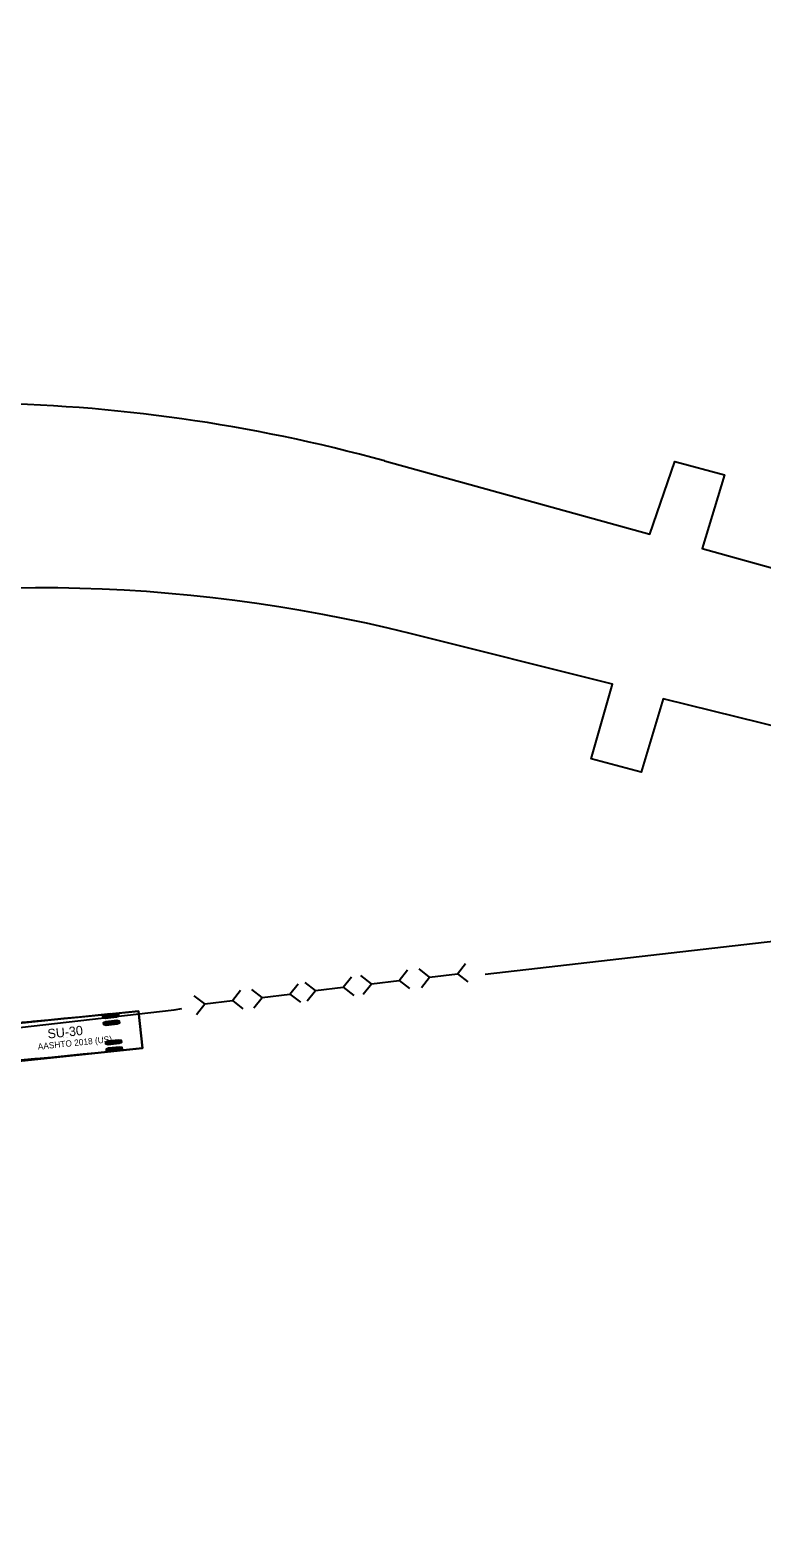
# Model space of a CAD drawing. Extents: x 1600240 to 1604759, y 285789 to 289704.
# Drawn here: x 1601319 to 1601475.5, y 286564.2 to 286886.8 of the extents above; entities that cross this region are included whole.
import ezdxf

# ---------------------------------------------------------------- set-up
doc = ezdxf.new("R2010")
doc.units = 0
for name, color, linetype in [('MT_P_Cells', 7, 'Continuous'), ('MT_P_CL_Double_Solid', 7, 'Continuous'), ('MT_X_CL_Double_Solid', 7, 'Continuous'), ('MT_X_Edge_Line', 7, 'Continuous'), ('PM_X_Edge_Line', 7, 'Continuous')]:
    doc.layers.add(name, color=color, linetype=linetype)

msp = doc.modelspace()

# ---------------------------------------------------------------- linework, layer by layer
at = {"layer": 'MT_P_Cells'}
for p, q in [((1601410.37, 286684.89), (1601412.12, 286687.12)), ((1601385.95, 286682.01), (1601387.7, 286684.24)), ((1601391.96, 286682.75), (1601389.73, 286684.5)), ((1601391.96, 286682.75), (1601397.91, 286683.47)), ((1601397.91, 286683.47), (1601399.66, 286685.7)), ((1601397.91, 286683.47), (1601400.14, 286681.73)), ((1601404.41, 286684.17), (1601402.19, 286685.92)), ((1601402.67, 286681.95), (1601404.41, 286684.17)), ((1601404.41, 286684.17), (1601410.37, 286684.89)), ((1601410.37, 286684.89), (1601412.6, 286683.15)), ((1601356.29, 286678.43), (1601354.06, 286680.18)), ((1601362.24, 286679.15), (1601363.99, 286681.38)), ((1601368.59, 286679.81), (1601366.36, 286681.56)), ((1601368.59, 286679.81), (1601374.54, 286680.53)), ((1601374.54, 286680.53), (1601376.29, 286682.76)), ((1601374.54, 286680.53), (1601376.77, 286678.79)), ((1601380, 286681.29), (1601377.77, 286683.04)), ((1601378.25, 286679.07), (1601380, 286681.29)), ((1601380, 286681.29), (1601385.95, 286682.01)), ((1601385.95, 286682.01), (1601388.18, 286680.27)), ((1601390.21, 286680.53), (1601391.96, 286682.75)), ((1601354.54, 286676.21), (1601356.29, 286678.43)), ((1601356.29, 286678.43), (1601362.24, 286679.15)), ((1601362.24, 286679.15), (1601364.47, 286677.41)), ((1601366.84, 286677.58), (1601368.59, 286679.81))]:
    msp.add_line(p, q, dxfattribs=at)
at = {"layer": 'MT_P_CL_Double_Solid'}
for p, q in [((1601342.12, 286676.92), (1601312.29, 286673.79)), ((1601342.96, 286668.97), (1601342.12, 286676.92)), ((1601334.52, 286675.92), (1601337.84, 286676.26)), ((1601334.54, 286675.71), (1601337.86, 286676.06)), ((1601334.56, 286675.5), (1601337.88, 286675.85)), ((1601334.68, 286674.42), (1601337.99, 286674.77)), ((1601334.7, 286674.22), (1601338.01, 286674.56)), ((1601334.72, 286674.01), (1601338.04, 286674.36)), ((1601335.11, 286670.28), (1601338.43, 286670.63)), ((1601335.13, 286670.07), (1601338.45, 286670.42)), ((1601313.12, 286665.84), (1601342.96, 286668.97)), ((1601335.16, 286669.87), (1601338.47, 286670.21)), ((1601335.27, 286668.79), (1601338.58, 286669.14)), ((1601335.29, 286668.58), (1601338.61, 286668.93)), ((1601335.31, 286668.37), (1601338.63, 286668.72))]:
    msp.add_line(p, q, dxfattribs=at)
for points in [[(1601317.91, 286674.52), (1601329.22, 286675.59), (1601342.12, 286676.92), (1601342.96, 286668.97), (1601341.53, 286668.81)], [(1601319.21, 286674.63), (1601316.26, 286674.37), (1601313.03, 286674.14), (1601309.8, 286673.96), (1601306.57, 286673.84), (1601303.34, 286673.79), (1601300.1, 286673.79), (1601296.87, 286673.86), (1601293.64, 286673.99), (1601290.74, 286674.16)], [(1601336.16, 286676.3), (1601332.84, 286675.95), (1601329.51, 286675.62), (1601326.19, 286675.29), (1601322.87, 286674.97), (1601319.54, 286674.66), (1601319.21, 286674.63)], [(1601341.53, 286668.81), (1601312.6, 286665.78)], [(1601336.99, 286668.34), (1601333.65, 286667.99), (1601330.31, 286667.66), (1601326.96, 286667.33), (1601323.62, 286667.01), (1601320.27, 286666.7), (1601319.94, 286666.67)], [(1601319.94, 286666.67), (1601316.92, 286666.4), (1601313.55, 286666.15), (1601310.17, 286665.97), (1601306.79, 286665.85), (1601303.4, 286665.79), (1601300.02, 286665.79), (1601296.63, 286665.87), (1601293.25, 286666), (1601290.21, 286666.18)]]:
    msp.add_lwpolyline(points, dxfattribs=at)
for points in [[(1601334.57, 286675.45), (1601334.52, 286675.97), (1601334.96, 286676.17), (1601337.35, 286676.42), (1601337.83, 286676.32), (1601337.88, 286675.8), (1601337.44, 286675.59), (1601335.05, 286675.34)], [(1601334.73, 286673.96), (1601334.67, 286674.48), (1601335.12, 286674.68), (1601337.51, 286674.93), (1601337.99, 286674.82), (1601338.04, 286674.31), (1601337.59, 286674.1), (1601335.21, 286673.85)], [(1601335.16, 286669.81), (1601335.11, 286670.33), (1601335.55, 286670.54), (1601337.94, 286670.79), (1601338.42, 286670.68), (1601338.48, 286670.16), (1601338.03, 286669.96), (1601335.64, 286669.71)], [(1601335.32, 286668.32), (1601335.26, 286668.84), (1601335.71, 286669.04), (1601338.1, 286669.29), (1601338.58, 286669.19), (1601338.63, 286668.67), (1601338.18, 286668.47), (1601335.8, 286668.22)]]:
    msp.add_lwpolyline(points, close=True, dxfattribs=at)
for centre in [(1601319.21, 286674.63), (1601319.21, 286674.63), (1601336.16, 286676.3), (1601336.99, 286668.34), (1601319.94, 286666.67), (1601319.94, 286666.67)]:
    msp.add_circle(centre, 0.0417, dxfattribs=at)
at = {"layer": 'MT_X_CL_Double_Solid'}
for p, q in [((1601416.32, 286684.84), (1601542.22, 286699.29)), ((1601295.56, 286671.01), (1601349.74, 286677.21)), ((1601349.74, 286677.21), (1601351.38, 286677.44))]:
    msp.add_line(p, q, dxfattribs=at)
at = {"layer": 'MT_X_Edge_Line'}
msp.add_arc((1602837.87, 287782.94), 1921, 229.7619, 229.7619, dxfattribs=at)
at = {"layer": 'PM_X_Edge_Line'}
for points in [[(1601394.74, 286794.62), (1601451.5, 286778.96), (1601456.84, 286794.53), (1601467.47, 286791.65), (1601462.74, 286775.88), (1601493.76, 286767.22)], [(1601501.83, 286731.99), (1601454.41, 286743.72), (1601449.64, 286728.05), (1601439, 286730.9), (1601443.51, 286746.88), (1601400.22, 286757.7)]]:
    msp.add_lwpolyline(points, dxfattribs=at)
for centre, radius, start, end in [((1601303.03, 286462.27), 344.77, 74.5736, 89.2879), ((1601320.92, 286440.5), 326.96, 75.9637, 102.6554)]:
    msp.add_arc(centre, radius, start, end, dxfattribs=at)

# ---------------------------------------------------------------- texts
at = {"layer": 'MT_P_CL_Double_Solid'}
for s, height, p in [('SU-30', 2, (1601322.78, 286671.03)), ('AASHTO 2018 (US)', 1.3333, (1601320.66, 286668.63)), ('(c) 2024 Transoft Solutions, Inc. All rights reserved.', 0.08, (1601326, 286671.17))]:
    msp.add_text(s, height=height, rotation=5.9907, dxfattribs=at).set_placement(p)

doc.saveas('drawing.dxf')
